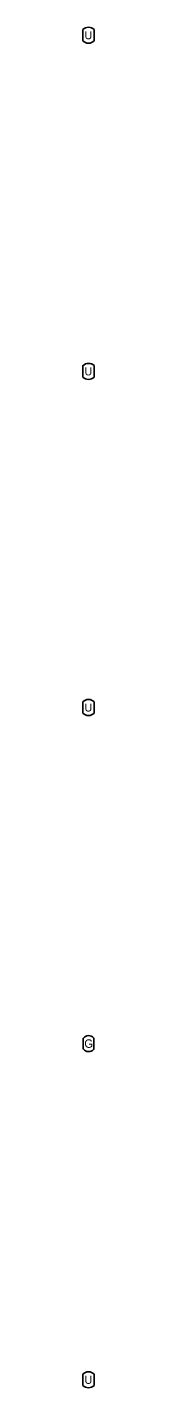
# Model space of a CAD drawing. Extents: x 98 to 2902, y -6 to 903.
# Drawn here: x 2699.2 to 2700.8, y -1.2 to 201.2 of the extents above; entities that cross this region are included whole.
import ezdxf

# ---------------------------------------------------------------- set-up
doc = ezdxf.new("R2010")
doc.units = 0
for name, color, linetype in [('V-FUEL-VALT', 7, 'Continuous'), ('V-SSWR-DEVC', 7, 'Continuous'), ('V-UTIL-VALT', 7, 'Continuous')]:
    doc.layers.add(name, color=color, linetype=linetype)

msp = doc.modelspace()

# ---------------------------------------------------------------- linework, layer by layer
at = {"layer": 'V-FUEL-VALT'}
for points in [[(2699.23, 50.81), (2699.23, 49.19)], [(2700.77, 49.15), (2700.77, 50.85)]]:
    msp.add_lwpolyline(points, dxfattribs=at)
for centre, start, end in [((2700.02, 50.19), 41.5928, 141.618), ((2700.02, 49.81), 218.382, 318.4072)]:
    msp.add_arc(centre, 1, start, end, dxfattribs=at)
at = {"layer": 'V-SSWR-DEVC'}
for p, q in [((2700.85, 150.85), (2700.85, 150.85)), ((2700.85, 100.85), (2700.85, 100.85))]:
    msp.add_line(p, q, dxfattribs=at)
for points in [[(2699.15, 150.85), (2699.15, 149.15)], [(2700.85, 149.15), (2700.85, 150.85)], [(2699.15, 100.85), (2699.15, 99.15)], [(2700.85, 99.15), (2700.85, 100.85)]]:
    msp.add_lwpolyline(points, dxfattribs=at)
for centre, start, end in [((2700, 149.97), 46.2405, 134.1843), ((2700, 150.03), 226.2449, 314.1799), ((2700, 99.97), 46.2405, 134.1843), ((2700, 100.03), 226.2449, 314.1799)]:
    msp.add_arc(centre, 1.22, start, end, dxfattribs=at)
at = {"layer": 'V-UTIL-VALT'}
for p, q in [((2700.85, 200.85), (2700.85, 200.85)), ((2700.85, 0.85), (2700.85, 0.85))]:
    msp.add_line(p, q, dxfattribs=at)
for points in [[(2699.15, 200.85), (2699.15, 199.15)], [(2700.85, 199.15), (2700.85, 200.85)], [(2699.15, 0.85), (2699.15, -0.85)], [(2700.85, -0.85), (2700.85, 0.85)]]:
    msp.add_lwpolyline(points, dxfattribs=at)
for centre, start, end in [((2700, 199.97), 46.2405, 134.1843), ((2700, 200.03), 226.2449, 314.1799), ((2700, -0.03), 46.2405, 134.1843), ((2700, 0.03), 226.2449, 314.1799)]:
    msp.add_arc(centre, 1.22, start, end, dxfattribs=at)

# ---------------------------------------------------------------- texts
at = {"layer": 'V-FUEL-VALT'}
msp.add_text('G', height=1.25, dxfattribs=at).set_placement((2699.38, 49.38))
at = {"layer": 'V-SSWR-DEVC'}
for p in [(2699.41, 149.4), (2699.41, 99.4)]:
    msp.add_text('U', height=1.19, dxfattribs=at).set_placement(p)
at = {"layer": 'V-UTIL-VALT'}
for p in [(2699.41, 199.4), (2699.41, -0.6)]:
    msp.add_text('U', height=1.19, dxfattribs=at).set_placement(p)

doc.saveas('drawing.dxf')
